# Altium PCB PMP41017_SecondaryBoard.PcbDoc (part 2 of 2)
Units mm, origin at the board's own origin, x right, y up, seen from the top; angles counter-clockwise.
Board outline 59.94 x 50.1 mm, 4 copper layers (Top Layer, Layer 1, Layer 2, Bottom Layer), stack 1.926 mm thick; 120 components, 60 nets, 831 pads, 509 vias.
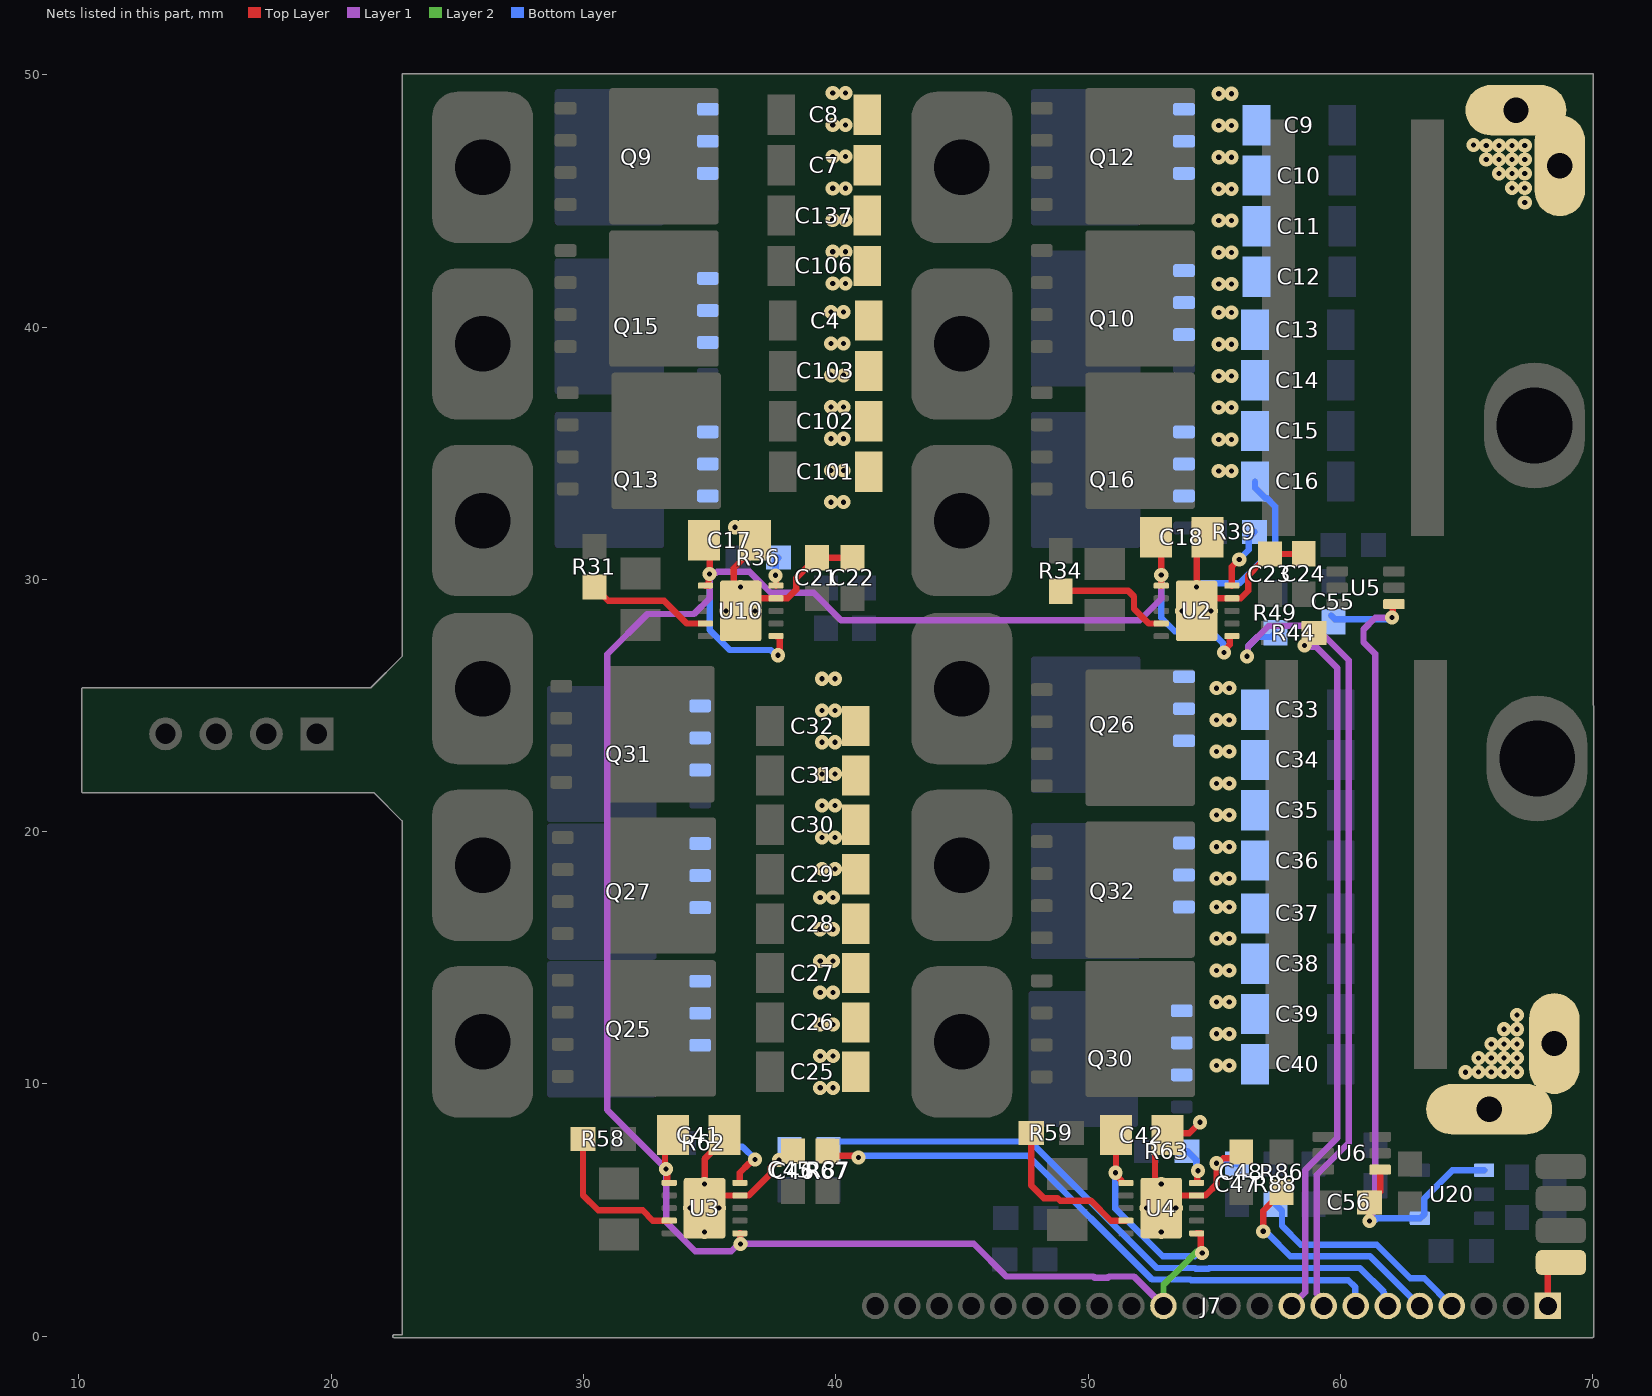
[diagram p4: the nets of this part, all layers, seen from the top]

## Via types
v1: diameter 0.559, hole 0.203, Top Layer to Bottom Layer, tented both sides, 490 vias
v2: diameter 0.559, hole 0.203, Top Layer to Bottom Layer, 14 vias
v3: diameter 0.7, hole 0.35, Top Layer to Bottom Layer, 4 vias
v4: diameter 0.762, hole 0.356, Top Layer to Bottom Layer, tented both sides, 1 vias

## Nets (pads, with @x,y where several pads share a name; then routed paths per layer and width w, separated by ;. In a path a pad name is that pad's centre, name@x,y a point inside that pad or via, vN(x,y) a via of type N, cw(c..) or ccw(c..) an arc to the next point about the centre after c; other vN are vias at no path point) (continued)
SR1_BH: J7.9 R44.1 | length 28.4
  Top Layer w0.254: v1(58.585,27.38) 58.585,27.531 58.933,27.879 R44.1@58.958,27.879
  Layer 1 w0.254: J7.9@58.07,1.2 58.611,1.74 58.611,6.59 59.878,7.858 59.878,26.489 59.036,27.331 58.634,27.331 v1(58.585,27.38)
SR1_BL: J7.8 R49.1 | length 33.2
  Layer 1 w0.254: v1(56.3,26.952) 56.34,26.992 56.34,27.338 57.163,28.161 58.965,28.161 60.332,26.793 60.332,7.67 59.065,6.402 59.065,1.691 59.34,1.415 J7.8@59.34,1.2
  Bottom Layer w0.254: v1(56.3,26.952) 56.34,26.992 56.34,27.338 56.719,27.717 57.261,27.717 R49.1@57.427,27.883
SR2_AH: J7.7 R67.1 | length 24
  Top Layer w0.254: R67.1@39.663,7.343 39.856,7.15 40.746,7.15 40.812,7.085 v1(40.894,7.085)
  Bottom Layer w0.254: v1(40.894,7.085) 40.941,7.132 41.115,7.132 41.133,7.15 47.633,7.15 52.533,2.251 54.055,2.251 54.085,2.221 60.317,2.221 60.587,1.95 60.587,1.223 J7.7@60.61,1.2
SR2_AL: J7.6 R87.1 | length 25.3
  Bottom Layer w0.254: R87.1@39.716,7.404 40.032,7.72 47.706,7.72 52.721,2.705 54.243,2.705 54.273,2.675 54.775,2.675 54.805,2.705 60.774,2.705 61.728,1.75 61.728,1.352 J7.6@61.88,1.2
SR2_BH: J7.5 R86.1 | length 9.3
  Top Layer w0.254: v1(56.946,4.159) 56.946,4.976 57.302,5.332 57.327,5.332 57.675,5.68 R86.1@57.675,5.705
  Bottom Layer w0.254: v1(56.946,4.159) 57.015,4.159 57.142,4.032 57.16,4.032 58.018,3.175 61.175,3.175 J7.5@63.15,1.2
SR2_BL: J7.4 R88.1 | length 9
  Bottom Layer w0.254: R88.1@57.427,5.23 57.689,4.968 57.689,4.374 58.434,3.629 61.439,3.629 62.776,2.293 63.328,2.293 J7.4@64.42,1.2
V0-out: C4.2 C7.2 C8.2 C9.2 C10.2 C11.2 C12.2 C13.2 C14.2 C15.2 C16.2 C17.2 C18.2 C21.1 C22.1 C23.1 C24.1 C25.2 C26.2 C27.2 C28.2 C29.2 C30.2 C31.2 C32.2 C33.2 C34.2 C35.2 C36.2 C37.2 C38.2 C39.2 C40.2 C41.2 C42.2 C45.1 C46.1 C47.1 C48.1 C101.2 C102.2 C103.2 C106.2 C137.2 J7.1 pad.4@65.9,9 pad.4@66.963,48.6 pad.4@68.7,46.4 pad.4@68.481,11.6 pad.9 Q9.1 Q9.2 Q9.3 Q10.1 Q10.2 Q10.3 Q12.1 Q12.2 Q12.3 Q13.1 Q13.2 Q13.3 Q15.1 Q15.2 Q15.3 Q16.1 Q16.2 Q16.3 Q25.1 Q25.2 Q25.3 Q26.1 Q26.2 Q26.3 Q27.1 Q27.2 Q27.3 Q30.1 Q30.2 Q30.3 Q31.1 Q31.2 Q31.3 Q32.1 Q32.2 Q32.3 U2.9 U2.11 U3.9 U3.11 U4.9 U4.11 U10.9 U10.11 | length 42.6
  Top Layer w0.254: U3.11@34.798,5.08 35.298,5.58 U3.9@36.198,5.58 36.551,5.58 37.4,6.429 37.4,6.683 37.701,6.984 37.962,6.984 38.032,7.055 C46.1@38.032,7.305 ; v2(34.798,6.03) 34.798,7.026 35.582,7.81 C41.2@35.582,7.975 ; C17.2@36.805,31.56 36.297,31.052 36.297,30.774 35.961,30.438 35.961,29.022 U10.11@36.23,28.753 36.73,29.253 38.089,29.253 38.426,29.589 38.426,30.049 38.862,30.485 38.898,30.485 39.246,30.833 C21.1@39.246,30.858 C22.1@40.666,30.858 ; U2.11@54.302,28.753 54.802,29.253 U2.9@55.702,29.253 56.055,29.253 56.351,29.549 56.351,30.154 56.832,30.635 56.857,30.635 57.205,30.983 C23.1@57.205,31.008 58.542,31.008 C24.1@58.55,31.016 ; v2(54.302,29.703) 54.302,31.141 C18.2@54.721,31.56 ; v1(54.443,8.481) 54.01,8.049 53.217,8.049 C42.2@53.143,7.975 52.652,7.484 52.652,5.33 U4.11@52.902,5.08 53.402,5.58 U4.9@54.302,5.58 54.641,5.58 54.694,5.633 54.708,5.633 55.091,6.016 55.091,6.857 55.157,6.858 55.355,7.056 55.824,7.056 C48.1@56.073,7.305 ; J7.1@68.23,1.2 68.23,2.537 68.594,2.901 pad.9@68.746,2.901
  Bottom Layer w0.254: v1(37.753,6.984) C45.1@38.173,7.404 ; v2(54.302,29.703) 54.384,29.703 54.534,29.852 56.005,29.852 57.427,31.274 57.427,32.883 57.1,33.21 57.041,33.21 56.618,33.633 C16.2@56.618,33.883 ; v1(55.09,6.858) 55.867,6.858 C47.1@55.895,6.83
  other v1: 39.382,9.847 39.89,9.847 64.969,10.464 65.477,10.475 65.985,10.475 66.493,10.475 67.001,10.475 55.09,10.731 55.598,10.731 65.477,11.032 65.985,11.033 66.493,11.033 67.001,11.033 39.382,11.105 39.89,11.105 65.985,11.581 66.493,11.581 67.001,11.581 55.09,11.988 55.598,11.988 66.493,12.167 67.001,12.167 39.382,12.362 39.89,12.362 67.001,12.73 55.09,13.246 55.598,13.246 39.382,13.62 39.89,13.62 55.09,14.503 55.598,14.503 39.382,14.877 39.89,14.877 55.09,15.76 55.598,15.76 39.382,16.135 39.89,16.135 55.09,17.018 55.598,17.018 39.382,17.392 39.89,17.392 55.09,18.143 55.598,18.143 39.457,18.518 39.965,18.518 55.09,19.401 55.598,19.401 39.457,19.775 39.965,19.775 55.09,20.658 55.598,20.658 39.457,21.032 39.965,21.032 55.09,21.916 55.598,21.916 39.457,22.29 39.965,22.29 55.09,23.173 55.598,23.173 39.457,23.547 39.965,23.547 55.09,24.431 55.598,24.431 39.457,24.805 39.965,24.805 55.09,25.688 55.598,25.688 39.457,26.062 39.965,26.062 36.006,32.067 39.803,33.061 40.311,33.061 55.181,34.294 55.689,34.294 39.803,34.319 40.311,34.319 55.181,35.551 55.689,35.551 39.803,35.576 40.311,35.576 55.181,36.808 55.689,36.808 39.803,36.834 40.311,36.834 55.181,38.066 55.689,38.066 39.803,38.091 40.311,38.091 55.181,39.323 55.689,39.323 39.803,39.348 40.311,39.348 55.181,40.581 55.689,40.581 39.803,40.606 40.311,40.606 55.181,41.706 55.689,41.706 39.878,41.732 40.386,41.732 55.181,42.964 55.689,42.964 39.878,42.989 40.386,42.989 55.181,44.221 55.689,44.221 39.878,44.246 40.386,44.246 67.31,44.948 55.181,45.479 55.689,45.479 39.878,45.504 40.386,45.504 66.802,45.511 67.31,45.511 66.294,46.097 66.802,46.097 67.31,46.097 65.786,46.646 66.294,46.645 66.802,46.645 67.31,46.645 55.181,46.736 55.689,46.736 39.878,46.761 40.386,46.761 65.278,47.214 65.786,47.203 66.294,47.203 66.802,47.203 67.31,47.203 55.181,47.993 55.689,47.993 39.878,48.019 40.386,48.019 55.181,49.251 55.689,49.251 39.878,49.276 40.386,49.276
  other v2: 34.798,4.13 52.902,4.13 34.223,5.08 35.373,5.08 52.327,5.08 53.477,5.08 52.902,6.03 35.655,28.753 36.805,28.753 53.727,28.753 54.877,28.753 36.23,29.703
VDD: C17.1 C18.1 C41.1 C42.1 J7.13 U2.1 U2.6 U3.1 U3.6 U4.1 U4.6 U10.1 U10.6 | length 101.2
  Top Layer w0.25: U3.1@33.398,6.08 33.393,6.085 33.323,6.085 33.323,6.582 v1(33.274,6.631) 33.234,6.672 33.234,7.658 C41.1@33.55,7.975 ; C42.1@51.111,7.975 51.111,6.507 v1(51.086,6.482) 51.086,6.412 51.327,6.171 U4.1@51.327,6.085
  Top Layer w0.254: C17.1@34.76,31.661 34.83,31.591 C17.1@34.83,31.503 ; C17.1@34.773,31.56 C17.1@34.83,31.503 ; U10.1@34.83,29.753 34.946,29.753 34.953,29.76 34.953,30.163 v1(35,30.21) 35,31.333 C17.1@34.83,31.503 ; U3.6@36.198,4.08 36.207,4.08 36.214,4.073 36.214,3.677 v1(36.23,3.661) ; U10.6@37.63,27.753 37.768,27.753 37.775,27.746 37.775,27.142 37.711,27.077 v1(37.711,26.995) ; C18.1@52.689,31.56 52.902,31.347 v1(52.902,30.178) U2.1@52.902,29.753 ; U4.6@54.302,4.08 54.468,4.08 54.475,4.073 54.475,3.346 v1(54.524,3.297) ; v1(55.395,27.108) 55.395,27.189 55.615,27.409 55.615,27.746 55.622,27.753 U2.6@55.702,27.753
  Layer 1 w0.254: v1(52.902,30.178) 52.902,29.238 52.051,28.387 40.207,28.387 39.126,29.468 37.424,29.468 36.583,30.309 35.301,30.309 35.26,30.268 35.058,30.268 v1(35,30.21) 35,29.248 34.381,28.63 32.534,28.63 30.935,27.031 30.935,8.97 v1(33.274,6.631) 33.274,4.527 34.43,3.371 35.857,3.371 36.147,3.661 v1(36.23,3.661) 45.463,3.661 46.756,2.368 50.215,2.368 50.272,2.311 50.774,2.311 50.832,2.368 51.822,2.368 J7.13@52.99,1.2
  Layer 2 w0.254: J7.13@52.99,1.2 52.99,2.038 53.633,2.681 54.295,3.342 54.297,3.339 54.482,3.339 v1(54.524,3.297)
  Bottom Layer w0.254: v1(35,30.21) 35,27.995 35.792,27.204 37.422,27.204 37.631,26.995 v1(37.711,26.995) ; v1(51.086,6.482) 51.086,5.049 52.959,3.175 54.223,3.175 54.287,3.239 54.466,3.239 v1(54.524,3.297) ; v1(52.902,30.178) 52.902,28.485 53.441,27.945 54.877,27.945 55.363,27.46 55.363,27.14 v1(55.395,27.108)
VG_SR1_AH: R31.1 U10.4 | length 5
  Top Layer w0.254: R31.1@30.43,29.703 30.43,29.678 30.778,29.33 30.803,29.33 30.977,29.156 33.194,29.156 34.097,28.253 U10.4@34.83,28.253
VG_SR1_AL: R36.1 U10.10 | length 1.2
  Top Layer w0.254: U10.10@37.63,29.753 37.63,30.17 v1@37.63,30.178
  Bottom Layer w0.254: v1(37.615,30.163) 37.615,30.753 R36.1@37.726,30.864
VG_SR1_BH: R34.1 U2.4 | length 4.8
  Top Layer w0.254: R34.1@48.917,29.534 48.926,29.543 51.601,29.543 51.821,29.323 51.821,28.839 52.407,28.253 U2.4@52.902,28.253
VG_SR1_BL: R39.1 U2.10 | length 2.6
  Top Layer w0.254: U2.10@55.702,29.753 55.702,30.503 v1(55.995,30.796) v1@55.93,30.796
  Bottom Layer w0.254: v1(55.995,30.796) 56.376,31.177 56.376,31.661 R39.1@56.6,31.884
VG_SR2_AH: R58.1 U3.4 | length 6.1
  Top Layer w0.254: R58.1@29.978,7.823 29.978,5.589 30.579,4.989 32.342,4.989 32.751,4.58 U3.4@33.398,4.58
VG_SR2_AL: R62.1 U3.10 | length 2.7
  Top Layer w0.254: U3.10@36.198,6.08 36.198,6.483 36.561,6.846 36.568,6.846 36.721,6.999 v1(36.803,6.999)
  Bottom Layer w0.254: R62.1@35.566,7.662 35.712,7.516 36.299,7.516 36.803,7.011 v1(36.803,6.999)
VG_SR2_BH: R59.1 U4.4 | length 6.4
  Top Layer w0.254: R59.1@47.747,8.059 47.747,5.975 48.245,5.477 48.785,5.477 48.893,5.369 50.116,5.369 50.905,4.58 U4.4@51.502,4.58
VG_SR2_BL: R63.1 U4.10 | length 1.5
  Top Layer w0.254: U4.10@54.302,6.08 54.324,6.08 54.331,6.087 54.331,6.531 v1(54.359,6.56)
  Bottom Layer w0.254: R63.1@53.917,7.332 53.942,7.332 54.29,6.984 54.29,6.695 54.359,6.626 v1(54.359,6.56)
Vref: C55.2 C56.2 U5.1 U6.1 U20.1 U20.4 | length 36.2
  Top Layer w0.254: v1(61.154,4.562) 61.154,5.063 61.278,5.186 C56.2@61.156,5.307 61.181,5.307 61.529,5.655 61.529,5.68 61.576,5.727 U6.1@61.576,6.605 ; v1(62.042,28.486) 62.084,28.527 62.084,28.947 62.157,29.02 U5.1@62.169,29.02
  Layer 1 w0.254: v1(61.154,4.562) 61.213,4.62 61.213,4.798 61.384,4.969 61.384,27.046 60.917,27.512 60.917,28.017 61.386,28.486 v1(62.042,28.486)
  Bottom Layer w0.254: C55.2@59.64,28.57 59.781,28.429 61.985,28.429 v1(62.042,28.486) ; v1(61.154,4.562) 61.213,4.62 61.393,4.62 61.452,4.679 U20.4@63.15,4.679 63.173,4.679 63.321,4.827 63.321,5.457 64.443,6.579 U20.1@65.7,6.579
pads on no net: Q1.9@31.279,44.4 Q1.9@31.279,49.145 Q1.9@31.574,45.442 Q1.9@31.574,46.772 Q1.9@31.574,48.102 Q1.9@32.724,45.442 Q1.9@32.724,46.772 Q1.9@32.724,48.102 Q1.9@32.859,46.772 Q1.9@33.874,45.442 Q1.9@33.874,46.772 Q1.9@33.874,48.102 Q2.9@50.153,38.76 Q2.9@50.153,43.505 Q2.9@50.448,39.803 Q2.9@50.448,41.133 Q2.9@50.448,42.463 Q2.9@51.598,39.803 Q2.9@51.598,41.133 Q2.9@51.598,42.463 Q2.9@51.733,41.133 Q2.9@52.748,39.803 Q2.9@52.748,41.133 Q2.9@52.748,42.463 Q4.9@50.153,44.4 Q4.9@50.153,49.145 Q4.9@50.448,45.442 Q4.9@50.448,46.772 Q4.9@50.448,48.102 Q4.9@51.598,45.442 Q4.9@51.598,46.772 Q4.9@51.598,48.102 Q4.9@51.733,46.772 Q4.9@52.748,45.442 Q4.9@52.748,46.772 Q4.9@52.748,48.102 Q5.9@31.366,33.121 Q5.9@31.366,37.866 Q5.9@31.661,34.163 Q5.9@31.661,35.493 Q5.9@31.661,36.823 Q5.9@32.811,34.163 Q5.9@32.811,35.493 Q5.9@32.811,36.823 Q5.9@32.946,35.493 Q5.9@33.961,34.163 Q5.9@33.961,35.493 Q5.9@33.961,36.823 Q7.9@31.279,38.76 Q7.9@31.279,43.505 Q7.9@31.574,39.803 Q7.9@31.574,41.133 Q7.9@31.574,42.463 Q7.9@32.724,39.803 Q7.9@32.724,41.133 Q7.9@32.724,42.463 Q7.9@32.859,41.133 Q7.9@33.874,39.803 Q7.9@33.874,41.133 Q7.9@33.874,42.463 Q8.9@50.153,33.121 Q8.9@50.153,37.866 Q8.9@50.448,34.163 Q8.9@50.448,35.493 Q8.9@50.448,36.823 Q8.9@51.598,34.163 Q8.9@51.598,35.493 Q8.9@51.598,36.823 Q8.9@51.733,35.493 Q8.9@52.748,34.163 Q8.9@52.748,35.493 Q8.9@52.748,36.823 Q9.9@30.344,45.402 Q9.9@30.344,46.732 Q9.9@30.344,48.062 Q9.9@31.359,46.732 Q9.9@31.494,45.402 Q9.9@31.494,46.732 Q9.9@31.494,48.062 Q9.9@32.644,45.402 Q9.9@32.644,46.732 Q9.9@32.644,48.062 Q9.9@32.939,44.36 Q9.9@32.939,49.105 Q10.9@49.218,39.007 Q10.9@49.218,40.337 Q10.9@49.218,41.667 Q10.9@50.233,40.337 Q10.9@50.368,39.007 Q10.9@50.368,40.337 Q10.9@50.368,41.667 Q10.9@51.518,39.007 Q10.9@51.518,40.337 Q10.9@51.518,41.667 Q10.9@51.813,37.965 Q10.9@51.813,42.71 Q12.9@49.218,45.402 Q12.9@49.218,46.732 Q12.9@49.218,48.062 Q12.9@50.233,46.732 Q12.9@50.368,45.402 Q12.9@50.368,46.732 Q12.9@50.368,48.062 Q12.9@51.518,45.402 Q12.9@51.518,46.732 Q12.9@51.518,48.062 Q12.9@51.813,44.36 Q12.9@51.813,49.105 Q13.9@30.344,32.613 Q13.9@30.344,33.943 Q13.9@30.344,35.273 Q13.9@31.359,33.943 Q13.9@31.494,32.613 Q13.9@31.494,33.943 Q13.9@31.494,35.273 Q13.9@32.644,32.613 Q13.9@32.644,33.943 Q13.9@32.644,35.273 Q13.9@32.939,31.57 Q13.9@32.939,36.315 Q15.9@30.344,38.698 Q15.9@30.344,40.028 Q15.9@30.344,41.358 Q15.9@31.359,40.028 Q15.9@31.494,38.698 Q15.9@31.494,40.028 Q15.9@31.494,41.358 Q15.9@32.644,38.698 Q15.9@32.644,40.028 Q15.9@32.644,41.358 Q15.9@32.939,37.656 Q15.9@32.939,42.401 Q16.9@49.218,32.613 Q16.9@49.218,33.943 Q16.9@49.218,35.273 Q16.9@50.233,33.943 Q16.9@50.368,32.613 Q16.9@50.368,33.943 Q16.9@50.368,35.273 Q16.9@51.518,32.613 Q16.9@51.518,33.943 Q16.9@51.518,35.273 Q16.9@51.813,31.57 Q16.9@51.813,36.315 Q17.9@31.112,21.488 Q17.9@31.112,26.233 Q17.9@31.407,22.531 Q17.9@31.407,23.861 Q17.9@31.407,25.191 Q17.9@32.557,22.531 Q17.9@32.557,23.861 Q17.9@32.557,25.191 Q17.9@32.692,23.861 Q17.9@33.707,22.531 Q17.9@33.707,23.861 Q17.9@33.707,25.191 Q18.9@50.156,21.352 Q18.9@50.156,26.097 Q18.9@50.451,22.394 Q18.9@50.451,23.724 Q18.9@50.451,25.054 Q18.9@51.601,22.394 Q18.9@51.601,23.724 Q18.9@51.601,25.054 Q18.9@51.736,23.724 Q18.9@52.751,22.394 Q18.9@52.751,23.724 Q18.9@52.751,25.054 Q21.9@31.166,9.834 Q21.9@31.166,14.579 Q21.9@31.461,10.876 Q21.9@31.461,12.206 Q21.9@31.461,13.536 Q21.9@32.611,10.876 Q21.9@32.611,12.206 Q21.9@32.611,13.536 Q21.9@32.746,12.206 Q21.9@33.761,10.876 Q21.9@33.761,12.206 Q21.9@33.761,13.536 Q22.9@50.153,9.81 Q22.9@50.153,14.555 Q22.9@50.448,10.852 Q22.9@50.448,12.182 Q22.9@50.448,13.512 Q22.9@51.598,10.852 Q22.9@51.598,12.182 Q22.9@51.598,13.512 Q22.9@51.733,12.182 Q22.9@52.748,10.852 Q22.9@52.748,12.182 Q22.9@52.748,13.512 Q23.9@31.166,15.492 Q23.9@31.166,20.237 Q23.9@31.461,16.534 Q23.9@31.461,17.864 Q23.9@31.461,19.194 Q23.9@32.611,16.534 Q23.9@32.611,17.864 Q23.9@32.611,19.194 Q23.9@32.746,17.864 Q23.9@33.761,16.534 Q23.9@33.761,17.864 Q23.9@33.761,19.194 Q24.9@50.153,15.33 Q24.9@50.153,20.075 Q24.9@50.448,16.372 Q24.9@50.448,17.702 Q24.9@50.448,19.032 Q24.9@51.598,16.372 Q24.9@51.598,17.702 Q24.9@51.598,19.032 Q24.9@51.733,17.702 Q24.9@52.748,16.372 Q24.9@52.748,17.702 Q24.9@52.748,19.032 Q25.9@30.037,10.838 Q25.9@30.037,12.168 Q25.9@30.037,13.498 Q25.9@31.052,12.168 Q25.9@31.187,10.838 Q25.9@31.187,12.168 Q25.9@31.187,13.498 Q25.9@32.337,10.838 Q25.9@32.337,12.168 Q25.9@32.337,13.498 Q25.9@32.632,9.795 Q25.9@32.632,14.54 Q26.9@49.218,22.908 Q26.9@49.218,24.238 Q26.9@49.218,25.568 Q26.9@50.233,24.238 Q26.9@50.368,22.908 Q26.9@50.368,24.238 Q26.9@50.368,25.568 Q26.9@51.518,22.908 Q26.9@51.518,24.238 Q26.9@51.518,25.568 Q26.9@51.813,21.866 Q26.9@51.813,26.611 Q27.9@30.037,16.293 Q27.9@30.037,17.623 Q27.9@30.037,18.953 Q27.9@31.052,17.623 Q27.9@31.187,16.293 Q27.9@31.187,17.623 Q27.9@31.187,18.953 Q27.9@32.337,16.293 Q27.9@32.337,17.623 Q27.9@32.337,18.953 Q27.9@32.632,15.251 Q27.9@32.632,19.996 Q30.9@49.125,9.665 Q30.9@49.125,10.995 Q30.9@49.125,12.325 Q30.9@50.14,10.995 Q30.9@50.275,9.665 Q30.9@50.275,10.995 Q30.9@50.275,12.325 Q30.9@51.72,8.622 Q30.9@51.72,13.367 Q30.9@51.425,9.665 Q30.9@51.425,10.995 Q30.9@51.425,12.325 Q31.9@30.037,21.749 Q31.9@30.037,23.079 Q31.9@30.037,24.409 Q31.9@31.052,23.079 Q31.9@31.187,21.749 Q31.9@31.187,23.079 Q31.9@31.187,24.409 Q31.9@32.337,21.749 Q31.9@32.337,23.079 Q31.9@32.337,24.409 Q31.9@32.632,20.707 Q31.9@32.632,25.452 Q32.9@49.218,16.318 Q32.9@49.218,17.648 Q32.9@49.218,18.978 Q32.9@50.233,17.648 Q32.9@50.368,16.318 Q32.9@50.368,17.648 Q32.9@50.368,18.978 Q32.9@51.518,16.318 Q32.9@51.518,17.648 Q32.9@51.518,18.978 Q32.9@51.813,15.275 Q32.9@51.813,20.02 U2.2 U3.2 U4.2 U10.2

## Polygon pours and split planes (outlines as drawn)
12Vout on Top Layer "TOP_LAYER_12VOUT_P055" (solid, remove dead copper, pour order 55): 60.873,10.479 64.206,10.479 67.814,14.087 69.74,14.087 69.74,16.013 69.74,43.568 67.814,43.568 64.32,47.062 64.32,49.756 60.873,49.756
V0-out on Top Layer "TOP_LAYER_V0-OUT_P070" (solid, remove dead copper, pour order 70): 62.758,7.786 62.758,9.955 66.655,13.851 69.74,13.851 69.74,8.78 68.746,7.786
12Vo_B on Top Layer "TOP_LAYER_12VO_B_P065" (solid, remove dead copper, pour order 65): 58.908,27.38 49.53,27.38 49.53,8.895 59.553,8.895 59.586,8.928 59.586,26.702
LV_SW2B on Top Layer "TOP_LAYER_LV_SW2B_P064" (solid, remove dead copper, pour order 64): 42.418,28.668 48.024,28.668 49.18,27.512 49.18,10.261 47.587,8.668 43.148,8.668 42.418,9.398
V0-out on Top Layer "TOP_LAYER_V0-OUT_P063" (solid, remove dead copper, pour order 63): 38.862,26.633 41.489,26.633 41.843,26.278 41.843,8.78 38.862,8.78
V0-out on Top Layer "TOP_LAYER_V0-OUT_P052" (solid, remove dead copper, pour order 52): 64.539,49.846 64.539,47.171 67.927,43.782 69.85,43.782 69.85,49.338 69.342,49.846
12Vo_B on Top Layer "TOP_LAYER_12VO_B_P060" (solid, remove dead copper, pour order 60): 30.789,26.633 37.239,26.633 38.02,25.852 38.02,9.074 31.113,9.074 30.789,9.398
LV_SW2A on Top Layer "TOP_LAYER_LV_SW2A_P058" (solid, remove dead copper, pour order 58): 22.999,28.668 28.144,28.668 30.109,26.704 30.109,9.398 28.769,8.059 22.999,8.059
12Vo_A on Top Layer "TOP_LAYER_12VO_A_P051" (solid, remove dead copper, pour order 51): 49.96,49.846 59.459,49.846 59.459,31.976 59.057,31.574 49.98,31.574 49.378,32.177 49.378,49.265
LV_SW1B on Top Layer "TOP_LAYER_LV_SW1B_P050" (solid, remove dead copper, pour order 50): 42.418,29.267 42.418,49.36 43.058,50 48.864,50 49.108,49.755 49.108,30.254 48.121,29.267
V0-out on Top Layer "TOP_LAYER_V0-OUT_P048" (solid, remove dead copper, pour order 48): 39.283,49.846 41.91,49.846 42.265,49.492 42.265,31.994 39.283,31.994
12Vo_A on Top Layer "TOP_LAYER_12VO_A_P047" (solid, remove dead copper, pour order 47): 38.704,49.846 38.704,41.633 38.704,31.085 31.269,31.085 30.309,32.045 30.309,49.156 31,49.846
LV_SW1A on Top Layer "TOP_LAYER_LV_SW1A_P044" (solid, remove dead copper, pour order 44): 22.86,50 30.309,50 30.309,31.56 28.083,29.333 24.272,29.333 22.999,30.607
V0-out on Bottom Layer "BOTTOM_LAYER_V0-OUT_P069" (solid, remove dead copper, pour order 69): 63.796,7.124 69.74,7.124 69.74,14.246 62.954,14.246 62.719,14.011 62.719,8.2
12Vout on Bottom Layer "BOTTOM_LAYER_12VOUT_P057" (solid, remove dead copper, pour order 57): 62.436,40.671 69.394,40.671 69.74,40.324 69.74,15.278 62.436,15.278
12Vo_B on Bottom Layer "BOTTOM_LAYER_12VO_B_P068" (solid, remove dead copper, pour order 68): 60.434,8.07 61.275,8.911 61.275,26.742 57.897,26.742 57.897,8.07
V0-out on Bottom Layer "BOTTOM_LAYER_V0-OUT_P067" (solid, remove dead copper, pour order 67): 53.708,27.46 56.196,27.46 57.427,26.229 57.427,8.07 52.99,8.07 52.99,26.742
LV_SW2B on Bottom Layer "BOTTOM_LAYER_LV_SW2B_P066" (solid, remove dead copper, pour order 66): 42.714,8.116 52.1,8.116 52.555,8.571 52.555,27.766 51.361,28.96 43.822,28.96 41.843,26.981 41.843,8.988
V0-out on Bottom Layer "BOTTOM_LAYER_V0-OUT_P062" (solid, remove dead copper, pour order 62): 34.007,10.056 35.075,8.988 41.519,8.988 41.519,26.458 41.481,26.495 34.273,26.495 34.007,26.229
LV_SW2A on Bottom Layer "BOTTOM_LAYER_LV_SW2A_P061" (solid, remove dead copper, pour order 61): 23.014,28.668 32.674,28.668 33.451,27.891 33.451,8.891 32.631,8.071 24.002,8.071 22.999,9.074
V0-out on Bottom Layer "BOTTOM_LAYER_V0-OUT_P054" (solid, remove dead copper, pour order 54): 69.342,40.965 62.436,40.965 62.436,49.846 69.342,49.846 69.85,49.338 69.85,41.473
V0-out on Bottom Layer "BOTTOM_LAYER_V0-OUT_P046" (solid, remove dead copper, pour order 46): 33.8,31.722 42.265,31.722 42.265,49.492 41.91,49.846 34.498,49.846 33.8,49.148
12Vo_A on Bottom Layer "BOTTOM_LAYER_12VO_A_P056" (solid, remove dead copper, pour order 56): 60.764,32.256 61.275,32.768 61.275,49.846 57.897,49.846 57.897,32.256
V0-out on Bottom Layer "BOTTOM_LAYER_V0-OUT_P053" (solid, remove dead copper, pour order 53): 53.086,49.846 57.205,49.846 57.205,40.128 57.205,33.324 56.6,32.718 53.467,32.718 53.277,32.909
LV_SW1B on Bottom Layer "BOTTOM_LAYER_LV_SW1B_P049" (solid, remove dead copper, pour order 49): 42.926,48.768 44.004,49.846 52.223,49.846 52.578,49.492 52.578,30.758 52.324,30.504 51.021,29.201 43.058,29.201 42.926,29.333
LV_SW1A on Bottom Layer "BOTTOM_LAYER_LV_SW1A_P045" (solid, remove dead copper, pour order 45): 22.999,49.846 33.101,49.846 33.8,49.148 33.8,30.325 32.655,29.181 24.425,29.181 23.014,30.592
LV_SW2A on Layer 1 "LAYER_1_LV_SW2A_P078" (solid, remove dead copper, pour order 78): 28.916,8.05 28.916,29.122 28.703,29.334 23.585,29.334 22.952,28.7 22.952,8.755 23.642,8.065
LV_SW1A on Layer 1 "LAYER_1_LV_SW1A_P077" (solid, remove dead copper, pour order 77): 28.914,29.046 28.914,49.788 28.702,50 23.584,50 22.95,49.366 22.95,29.421 23.309,29.062
V0-out on Layer 1 "LAYER_1_V0-OUT_P076" (solid, remove dead copper, pour order 76): 63.669,4.868 69.74,4.868 69.74,14.246 62.954,14.246 62.719,14.011 62.719,5.817
12Vout on Layer 1 "LAYER_1_12VOUT_P075" (solid, remove dead copper, pour order 75): 60.972,40.671 69.394,40.671 69.74,40.324 69.74,15.278 60.972,15.278
V0-out on Layer 1 "LAYER_1_V0-OUT_P074" (solid, remove dead copper, pour order 74): 69.342,40.965 60.972,40.965 60.972,49.846 69.342,49.846 69.85,49.338 69.85,41.473
12Vo_B on Layer 1 "LAYER_1_12VO_B_P071" (solid, remove dead copper, pour order 71): 30.681,6.482 58.596,6.482 60.566,8.452 60.566,28.194 30.756,28.194
12Vo_A on Layer 1 "LAYER_1_12VO_A_P059" (solid, remove dead copper, pour order 59): 28.914,28.956 58.991,28.956 60.565,30.53 60.565,49.938 60.503,50 28.987,50
V0-out on Layer 2 "Layer 2-V0-out" (solid, remove dead copper, pour order 72): 28.956,0.476 69.981,0.476 69.981,16.98 64.269,16.98 62.423,18.826 62.422,39.662 63.781,41.022 69.98,41.022 69.98,50 28.956,50
LV_SW2A on Layer 2 "LAYER_2_LV_SW2A_P080" (solid, remove dead copper, pour order 80): 28.916,7.998 28.916,29.122 28.703,29.334 23.585,29.334 22.952,28.7 22.952,8.755 23.694,8.013
LV_SW1A on Layer 2 "LAYER_2_LV_SW1A_P079" (solid, remove dead copper, pour order 79): 28.914,29.046 28.914,49.788 28.702,50 23.584,50 22.95,49.366 22.95,29.421 23.309,29.062
12Vout on Layer 2 "LAYER_2_12VOUT_P073" (solid, remove dead copper, pour order 73): 69.996,17.267 64.401,17.267 62.738,18.93 62.738,39.624 63.885,40.771 69.791,40.771 69.981,40.581

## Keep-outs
Keep-Out Layer:
  text ".Layer_Name" at -20.343,-59.464 h1.52

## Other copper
Top Layer:
  text ".Layer_Name" at -20.343,-59.464 h1.52
Bottom Layer:
  text ".Layer_Name" at -20.343,-59.464 h1.52

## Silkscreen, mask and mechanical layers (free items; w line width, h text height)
Top Overlay:
  text "'.PRJ_Number'.PCB_Rev" at 24.384,0.762 h2.75
  text ".Layer_Name" at -20.343,-59.464 h1.52
Bottom Overlay:
  text ".Layer_Name" at -20.343,-59.464 h1.52
Top Paste:
  text ".Layer_Name" at -20.343,-59.464 h1.52
Bottom Paste:
  text ".Layer_Name" at -20.343,-59.464 h1.52
Top Solder:
  text ".Layer_Name" at -20.343,-59.464 h1.52
  text ".Layer_Name" at -20.343,-59.464 h1.52
Bottom Solder:
  text ".Layer_Name" at -20.343,-59.464 h1.52
Drill Guide:
  text ".Layer_Name" at -20.343,-59.464 h1.52
M1 Board Outline:
  lines w0.1: 22.479,0 70,0 69.98,50 22.86,50 22.86,26.924 21.59,25.654 10.16,25.654 10.16,21.59 21.336,21.59 21.717,21.59 22.86,20.447 22.86,0 ; 69.98,0 69.98,0
  text ".Layer_Name" at -20.343,-59.464 h1.52
M2 Board Dimensions:
  rectangle: -34.999,-44.643 -31.824,-41.468
  rectangle: -31.824,-47.818 -22.299,-44.643
  lines w0.178: -34.999,-44.643 -9.599,-44.643 ; -31.824,-47.818 -31.824,-41.468 ; -28.649,-47.818 -28.649,-41.468 ; -22.299,-47.818 -22.299,-41.468 ; -15.949,-47.818 -15.949,-41.468 ; -34.999,-47.818 -9.599,-47.818 -9.599,-41.468 -34.999,-41.468 -34.999,-47.818
  text ".Layer_Name" at -20.343,-59.464 h1.52
M3 3D STEP Top:
  text ".Layer_Name" at -20.343,-59.464 h1.52
M4 3D STEP Bottom:
  text ".Layer_Name" at -20.343,-59.464 h1.52
M5 Assembly Top:
  lines w0.254: -42.416,-61.285 125.224,-61.285 ; -42.416,-56.12 125.275,-56.12 ; -42.416,-50.955 -42.416,-66.449 59.311,-66.449 125.275,-66.449 125.275,-50.955 -42.403,-50.955 -42.403,-66.449 -2.386,-66.449 ; 20.195,-66.449 20.195,-50.955 ; 52.377,-56.12 52.377,-50.955 ; 73.713,-56.12 73.713,-50.955 ; 89.512,-66.614 89.512,-61.463
  text "COMPONENTS MARKED 'DNP' SHOULD NOT BE POPULATED." at -5.7,-45.748 h1.52
  text "ASSEMBLY VARIANT:" at -5.713,-48.682 h1.52
  text ".VariantName" at 20.601,-48.682 h1.52
  text "PCB VIEWED FROM TOP SIDE" at -40.803,-54.312 h1.52
  text "BOARD #:" at 22.1,-54.312 h1.52
  text ".PRJ_Number" at 35.956,-54.312 h1.52
  text "REV:" at 57.406,-54.312 h1.52
  text ".PCB_Rev" at 64.81,-54.312 h1.52
  text "SVN REV:" at 78.691,-54.312 h1.52
  text ".VersionControl_RevNumber" at 91.544,-54.312 h1.52
  text "TID #:" at 22.1,-59.477 h1.52
  text ".TID" at 35.956,-59.477 h1.52
  text "PLOT NAME =" at -40.803,-64.693 h1.52
  text ".plot_File_Name" at -20.343,-64.693 h1.52
  text "GENERATED    :" at 22.151,-64.693 h1.52
  text ".Print_Date" at 44.236,-64.693 h1.52
  text ".Print_Time" at 62.753,-64.693 h1.52
  text "TEXAS INSTRUMENTS" at 94.871,-64.693 h1.52
M6 Assembly Bottom:
  lines w0.254: -42.429,-56.133 125.262,-56.133 ; -42.378,-61.297 125.262,-61.297 ; -6.665,-66.627 -6.665,-61.475 ; 9.133,-56.133 9.133,-50.968 ; 30.469,-56.133 30.469,-50.968 ; 62.651,-66.462 62.651,-50.968 ; 85.232,-66.462 125.249,-66.462 125.249,-50.968 -42.429,-50.968 -42.429,-66.462 23.535,-66.462 125.262,-66.462 125.262,-50.968
  text "COMPONENTS MARKED 'DNP' SHOULD NOT BE POPULATED." at 119.992,-45.736 h1.52
  text ".VariantName" at 93.474,-48.682 h1.52
  text "ASSEMBLY VARIANT:" at 119.865,-48.682 h1.52
  text ".VersionControl_RevNumber" at -8.697,-54.325 h1.52
  text "SVN REV:" at 4.155,-54.325 h1.52
  text ".PCB_Rev" at 18.036,-54.325 h1.52
  text "REV:" at 25.44,-54.325 h1.52
  text ".PRJ_Number" at 46.89,-54.325 h1.52
  text "BOARD #:" at 60.746,-54.325 h1.52
  text "PCB VIEWED FROM BOTTOM SIDE" at 123.649,-54.325 h1.52
  text ".TID" at 46.89,-59.49 h1.52
  text "TID #:" at 60.746,-59.49 h1.52
  text "TEXAS INSTRUMENTS" at -12.025,-64.705 h1.52
  text ".Print_Time" at 20.093,-64.705 h1.52
  text ".Print_Date" at 38.61,-64.705 h1.52
  text "GENERATED    :" at 60.695,-64.705 h1.52
  text ".plot_File_Name" at 103.19,-64.705 h1.52
  text "PLOT NAME =" at 123.649,-64.705 h1.52
M9 Title Sheet:
  drawing of 57 lines, arcs and shapes, not listed
  text "1" at -16.207,166.469 h1.78
  text "2" at 47.183,166.469 h1.78
  text "3" at 110.412,166.469 h1.78
  text "4" at 174.081,166.469 h1.78
  text "5" at 237.556,166.469 h1.78
  text "6" at 301.183,166.469 h1.78
  text "A" at -45.578,137.436 h1.78
  text "A" at 330.342,137.436 h1.78
  text "B" at -45.578,76.984 h1.78
  text "B" at 330.342,76.984 h1.78
  text "C" at -45.578,16.659 h1.78
  text "C" at 330.342,16.659 h1.78
  text "PROJECT TITLE:" at 253.126,-30.61 h1.14
  text ".PRJ_Title" at 254.396,-33.996 h1.78
  text "DESIGNED FOR:" at 253.126,-38.255 h1.14
  text ".PRJ_Customer" at 254.396,-41.811 h1.78
  text "D" at -45.578,-43.539 h1.78
  text "D" at 330.342,-43.539 h1.78
  text "FILE NAME:" at 253.126,-45.875 h1.14
  text ".PCB_File_Name_No_Path" at 254.396,-48.923 h1.78
  text "Texas Instruments (TI) and/or its licensors do not warrant the accuracy or completeness of this specification" at 126.9,-53.034 h1.14
  text "ENGINEER:" at 253.126,-53.241 h1.14
  text "LAYOUT BY:" at 291.353,-53.241 h1.14
  text "or any information contained therein. TI and/or its licensors do not warrant that this design will meet" at 125.758,-55.896 h1.14
  text ".PRJ_Engineer" at 254.396,-57.178 h1.78
  text ".PCB_Layout" at 292.635,-57.178 h1.78
  text "the specifications, will be suitable for your application or fit for any particular purpose, or will operate in" at 125.758,-58.757 h1.14
  text ".Layer_Name" at -20.343,-59.464 h1.52
  text "ALTIUM DESIGNER VERSION:" at 291.353,-61.115 h1.14
  text "an implementation. TI and/or its licensors do not warrant that the design is production worthy. You should" at 125.758,-61.619 h1.14
  text "completely validate and test your design implementation to confirm the system functionality for your application." at 126.9,-64.481 h1.14
  text ".print_Scale" at 254.396,-64.502 h1.78
  text ".Application_BuildNumber" at 292.635,-64.502 h1.78
  text "1" at -16.207,-69.751 h1.78
  text "2" at 47.183,-69.751 h1.78
  text "3" at 110.412,-69.751 h1.78
  text "4" at 174.081,-69.751 h1.78
  text "5" at 237.556,-69.751 h1.78
  text "6" at 301.183,-69.751 h1.78
M10 Fab Notes:
  drawing of 189 lines, arcs and shapes, not listed
  text "DESIGN INFORMATION" at 279.504,123.788 h1.52
  text "MIN. TRACK WIDTH:" at 263.132,120.432 h1.52
  text "8" at 290.977,120.432 h1.52
  text "MIL" at 294.908,120.432 h1.52
  text "7.874" at 286.751,117.342 h1.52
  text "MIN. CLEARANCE:" at 263.132,117.28 h1.52
  text "MIL" at 294.908,117.28 h1.52
  text "MIN. VIA PAD SIZE:" at 263.132,114.127 h1.52
  text "24" at 290.215,114.127 h1.52
  text "MIL" at 294.908,114.127 h1.52
  text "0.05mm (2MIL)" at 280.785,110.827 h1.52
  text "MINIMUM ANNULAR RING" at 254.77,110.618 h1.52
  text "EXTERNAL" at 298.769,110.618 h1.52
  text "PER" at 259.85,107.821 h1.52
  text "IPC-D-275 CLASS 2 LEVEL C" at 265.438,107.821 h1.52
  text "MIL, HOLES" at 303.239,105.269 h1.52
  text "+/-" at 293.27,105.051 h1.52
  text "+/-" at 314.962,105.051 h1.52
  text "REGISTRATION TOLERANCES:" at 254.77,105.024 h1.52
  text "METAL" at 285.244,105.024 h1.52
  text "5" at 299.88,105.024 h1.52
  text "3" at 321.038,105.024 h1.52
  text "MIL" at 323.991,105.024 h1.52
  text "HOLE SIZE TOLERANCE (UNLESS OTHERWISE SPECIFIED):" at 254.77,102.527 h1.52
  text "+/-" at 314.962,102.454 h1.52
  text "3" at 321.038,102.427 h1.52
  text "MIL" at 323.991,102.427 h1.52
  text "MATERIAL:" at 252.871,98.931 h1.52
  text "FR-4 High Tg" at 277.926,95.666 h1.52
  text "X" at 274.258,95.463 h1.52
  text "FR-408" at 263.564,95.348 h1.52
  text "OTHER" at 301.359,95.348 h1.52
  text "62 MIL (1.6mm) +/-10%" at 271.695,91.715 h1.52
  text "X" at 268.644,91.653 h1.52
  text "THICKNESS:" at 254.77,91.507 h1.52
  text "OTHER" at 304.331,91.507 h1.52
  text "TOLERANCE:" at 254.77,87.993 h1.52
  text "X" at 276.315,87.993 h1.52
  text "ANSI IPC-6012 TYPE 3 CLASS 2" at 280.837,87.993 h1.52
  text "OTHER +/-" at 280.836,84.331 h1.52
  text "BOW & TWIST:" at 254.77,80.643 h1.52
  text "X" at 276.315,80.643 h1.52
  text "ANSI IPC-6012 TYPE 3 CLASS 2" at 280.837,80.643 h1.52
  text "OTHER +/-" at 280.836,76.917 h1.52
  text "DRILLING:" at 252.871,73.599 h1.52
  text "NC_DRILL FILES" at 297.6,70.928 h1.52
  text "REFERENCE:" at 254.77,70.828 h1.52
  text "X" at 271.464,70.825 h1.52
  text "AS SHOWN" at 275.985,70.828 h1.52
  text "X" at 294.349,70.828 h1.52
  text "OTHER" at 305.169,67.214 h1.52
  text "PTH COPPER THICKNESS:" at 254.762,67.125 h1.52
  text "X" at 283.698,67.125 h1.52
  text "20-30 um" at 286.949,67.125 h1.52
  text "BOARD FINISH:" at 252.871,63.376 h1.52
  text "SILKSCREEN:" at 256.813,60.579 h1.52
  text "X" at 281.141,60.579 h1.52
  text "TOP" at 284.113,60.579 h1.52
  text "X" at 294.095,60.579 h1.52
  text "BOTTOM" at 297.092,60.579 h1.52
  text "SILKSCREEN COLOR:" at 256.813,56.637 h1.52
  text "X" at 281.116,56.637 h1.52
  text "WHITE" at 284.113,56.637 h1.52
  text "OTHER" at 297.092,56.637 h1.52
  text "X" at 284.443,52.993 h1.52
  text "GREEN" at 287.44,52.993 h1.52
  text "OTHER" at 303.137,52.993 h1.52
  text "SOLDER RESIST COLOR:" at 256.813,52.819 h1.52
  text "X" at 284.443,49.075 h1.52
  text "MATTE" at 287.44,49.075 h1.52
  text "SEMI-GLOSS" at 303.126,49.059 h1.52
  text "IMMERSION GOLD (ENIG)" at 279.82,44.687 h1.52
  text "ENEPIG" at 313.794,44.503 h1.52
  text "SURFACE FINISH:" at 252.871,44.478 h1.52
  text "X" at 275.299,44.478 h1.52
  text "IMM. TIN/SILVER OR EQUIV" at 261.241,40.99 h1.52
  text "OTHER" at 297.6,40.89 h1.52
  text "ARRAY/PANEL:" at 252.871,36.944 h1.52
  text "CUT AND TRIM PER M1 BOARD OUTLINE" at 279.82,36.735 h1.52
  text "N.C. ROUTE" at 279.82,33.281 h1.52
  text "X" at 297.295,33.281 h1.52
  text "V. SCORE" at 301.817,33.281 h1.52
  text "CERTIFICATION:" at 252.871,30.001 h1.52
  text "MATERIALS AND WORKMANSHIP FOR ALL PCBS" at 271.286,30.001 h1.52
  text "TO MEET OR EXCEED THE REQUIREMENTS OF:" at 271.286,27.612 h1.52
  text "X" at 262.078,24.345 h1.52
  text "ANSI IPC-A-600F CLASS ->" at 265.33,24.345 h1.52
  text "X" at 307.189,24.345 h1.52
  text "2" at 309.983,24.345 h1.52
  text "1" at 301.982,24.307 h1.52
  text "3" at 318.974,24.307 h1.52
  text "X" at 282.703,20.594 h1.52
  text "RoHS" at 285.954,20.594 h1.52
  text "OTHER" at 302.322,20.594 h1.52
  text "PER ORDER" at 312.407,20.594 h1.52
  text "ALL BOARDS MUST MEET OR EXCEED UL94-V0 REQUIREMENTS." at 253.57,16.687 h1.52
  text "PCB MUST BEAR THE UL94V-0 UL REGISTERED MATERIAL ID NUMBER" at 253.57,13.739 h1.52
  text "ADDITIONAL REQUIREMENTS:" at 252.871,9.435 h1.52
  text "MICROSECTION:" at 254.77,6.714 h1.52
  text "YES" at 277.776,6.714 h1.52
  text "REQUIRED" at 299.658,3.048 h1.52
  text "BARE BOARD ELEC. TEST:" at 254.77,2.976 h1.52
  text "NONE" at 287.936,2.976 h1.52
  text "X" at 296.66,2.976 h1.52
  text "PER ORDER" at 314.694,2.976 h1.52
  text "XX MIL VIAS REQUIRE NON-CONDUCTIVE FILL AND PLANARIZE" at 259.041,-2.23 h1.5
  text "XX MIL VIAS REQUIRE CONDUCTIVE FILL AND PLANARIZE" at 259.244,-4.871 h1.52
  text "OUTER XX MIL TRACES REQUIRE 50 OHM SINGLE-ENDED IMPEDANCE" at 259.219,-9.021 h1.47
  text "LAYER 2 & 3 (INNER LAYERS) XX MIL WIDE, XX MIL SPACE / TRACES REQUIRE 100 OHM DIFFERENTIAL IMPEDANCE" at 259.016,-15.008 h1.52
  text ".Layer_Name" at -20.343,-59.464 h1.52
M11 Gerber Information:
  lines w0.254: -42.416,-61.285 125.224,-61.285 ; -42.416,-56.12 125.275,-56.12 ; -42.416,-50.955 -42.416,-66.449 59.311,-66.449 125.275,-66.449 125.275,-50.955 -42.403,-50.955 -42.403,-66.449 -2.386,-66.449 ; 20.195,-66.449 20.195,-50.955 ; 52.377,-56.12 52.377,-50.955 ; 73.713,-56.12 73.713,-50.955 ; 89.512,-66.614 89.512,-61.463
  text "ALL ARTWORK VIEWED FROM TOP SIDE" at -40.803,-54.312 h1.52
  text "BOARD #:" at 22.1,-54.312 h1.52
  text ".PRJ_Number" at 35.956,-54.312 h1.52
  text "REV:" at 57.406,-54.312 h1.52
  text ".PCB_Rev" at 64.81,-54.312 h1.52
  text "SVN REV:" at 78.691,-54.312 h1.52
  text ".VersionControl_RevNumber" at 91.544,-54.312 h1.52
  text "LAYER NAME =" at -40.803,-59.464 h1.52
  text "TID #:" at 22.1,-59.477 h1.52
  text ".TID" at 35.956,-59.477 h1.52
  text "PLOT NAME =" at -40.803,-64.693 h1.52
  text ".plot_File_Name" at -20.343,-64.693 h1.52
  text "GENERATED    :" at 22.151,-64.693 h1.52
  text ".Print_Date" at 44.236,-64.693 h1.52
  text ".Print_Time" at 62.753,-64.693 h1.52
  text "TEXAS INSTRUMENTS" at 94.871,-64.693 h1.52
M12 Stackup:
  drawing of 337 lines, arcs and shapes, not listed
  text "Layer" at 214.469,162.365 h1.52
  text "Name" at 224.881,162.365 h1.52
  text "Material" at 248.497,162.365 h1.52
  text "Thickness" at 270.335,162.365 h1.52
  text "Constant" at 286.841,162.365 h1.52
  text "Board Layer Stack" at 301.315,162.365 h1.52
  text "Top Overlay" at 224.881,159.317 h1.52
  text "Top Solder" at 224.881,156.269 h1.52
  text "Solder Resist" at 248.497,156.269 h1.52
  text "0.40mil" at 270.335,156.269 h1.52
  text "3.5" at 286.841,156.269 h1.52
  text "1" at 214.469,153.221 h1.52
  text "Top Layer" at 224.881,153.221 h1.52
  text "CF-005" at 248.497,153.221 h1.52
  text "2.76mil" at 270.335,153.221 h1.52
  text "Dielectric 1" at 224.881,150.173 h1.52
  text "PP-006" at 248.497,150.173 h1.52
  text "2.80mil" at 270.335,150.173 h1.52
  text "4.1" at 286.841,150.173 h1.52
  text "2" at 214.469,147.125 h1.52
  text "Layer 1" at 224.881,147.125 h1.52
  text "CF-005" at 248.497,147.125 h1.52
  text "2.76mil" at 270.335,147.125 h1.52
  text "Dielectric1" at 224.881,144.077 h1.52
  text "FR-4 High Tg" at 248.497,144.077 h1.52
  text "59.20mil" at 270.335,144.077 h1.52
  text "4.8" at 286.841,144.077 h1.52
  text "3" at 214.469,141.029 h1.52
  text "Layer 2" at 224.881,141.029 h1.52
  text "CF-005" at 248.497,141.029 h1.52
  text "2.76mil" at 270.335,141.029 h1.52
  text "Dielectric 2" at 224.881,137.981 h1.52
  text "PP-006" at 248.497,137.981 h1.52
  text "2.80mil" at 270.335,137.981 h1.52
  text "4.1" at 286.841,137.981 h1.52
  text "4" at 214.469,134.933 h1.52
  text "Bottom Layer" at 224.881,134.933 h1.52
  text "CF-005" at 248.497,134.933 h1.52
  text "2.76mil" at 270.335,134.933 h1.52
  text "Bottom Solder" at 224.881,131.885 h1.52
  text "Solder Resist" at 248.497,131.885 h1.52
  text "0.40mil" at 270.335,131.885 h1.52
  text "3.5" at 286.841,131.885 h1.52
  text "Bottom Overlay" at 224.881,128.837 h1.52
  text "GaN Board2" at 7.848,45.352 h0.89
  text "Transformer1" at 32.648,38.752 h0.89
  text "Resonant Choke 1&2" at 3.648,33.652 h0.89
  text "Board_CST" at 7.178,20.129 h0.89
  text "Transformer2" at 33.848,18.252 h0.89
  text "GaN Board1" at 6.448,12.152 h0.89
  text "Flyback" at 12.657,4.449 h0.89
  text "McU Board" at 49.457,2.352 h0.89
  text ".Layer_Name" at -20.343,-59.464 h1.52
M13 Component Bodies Top:
  text ".Layer_Name" at -20.343,-59.464 h1.52
M14 Component Bodies Bottom:
  text ".Layer_Name" at -20.343,-59.464 h1.52
M15 Courtyards Top:
  text ".Layer_Name" at -20.343,-59.464 h1.52
M16 Courtyards Bottom:
  text ".Layer_Name" at -20.343,-59.464 h1.52
Drill Drawing:
  lines w0.254: 91.775,24.712 92.125,24.712 92.125,24.362 92.827,24.362 92.827,24.712 93.178,24.712 93.178,25.414 92.827,25.414 92.827,25.765 92.125,25.765 92.125,25.414 91.775,25.414 91.775,24.712 ; 91.775,27.87 92.125,27.87 92.125,27.519 92.827,27.519 92.827,27.87 93.178,27.87 93.178,28.572 92.827,28.572 92.827,28.923 92.125,28.923 92.125,28.572 91.775,28.572 91.775,27.87 ; 91.775,33.835 91.775,34.186 92.125,34.537 91.775,34.887 91.775,35.238 92.125,35.238 92.476,34.887 92.827,35.238 93.178,35.238 93.178,34.887 92.827,34.537 93.178,34.186 93.178,33.835 92.827,33.835 92.476,34.186 92.125,33.835 91.775,33.835 ; 91.775,38.396 93.178,38.396 92.476,36.993 91.775,38.396 ; 91.775,40.501 92.125,40.501 92.476,40.15 92.827,40.501 93.178,40.501 92.827,40.852 93.178,41.203 92.827,41.203 92.476,41.554 92.125,41.203 91.775,41.203 92.125,40.852 91.775,40.501 ; 91.775,43.308 93.178,43.308 93.178,44.711 91.775,44.711 91.775,43.308 ; 92.055,28.011 92.266,28.011 92.266,27.8 92.687,27.8 92.687,28.011 92.897,28.011 92.897,28.432 92.687,28.432 92.687,28.642 92.266,28.642 92.266,28.432 92.055,28.432 92.055,28.011 ; 92.055,34.115 92.055,34.326 92.266,34.537 92.055,34.747 92.055,34.958 92.266,34.958 92.476,34.747 92.687,34.958 92.897,34.958 92.897,34.747 92.687,34.537 92.897,34.326 92.897,34.115 92.687,34.115 92.476,34.326 92.266,34.115 92.055,34.115
  lines w0.305: 90.502,17.099 172.582,17.099 ; 90.502,45.518 172.582,45.518 ; 99.084,13.941 99.084,48.676 ; 107.517,13.941 107.517,48.676 ; 123.685,13.941 123.685,48.676 ; 130.268,13.941 130.268,48.676 ; 139.797,13.941 139.797,48.676 ; 158.195,13.941 158.195,48.676 ; 90.502,13.941 172.582,13.941 172.582,48.676 90.502,48.676 90.502,13.941
  text "Symbol" at 92.397,46.466 h1.83
  text "Quantity" at 100.031,46.466 h1.83
  text "Finished Hole Size" at 108.464,46.466 h1.83
  text "Plated" at 124.633,46.466 h1.83
  text "Hole Type" at 131.215,46.466 h1.83
  text "Drill Layer Pair" at 140.744,46.466 h1.83
  text "Hole Tolerance" at 159.142,46.466 h1.83
  text "504" at 100.031,43.308 h1.52
  text "8.00mil (0.203mm)" at 108.464,43.308 h1.52
  text "PTH" at 124.633,43.308 h1.52
  text "Round" at 131.215,43.308 h1.52
  text "Top Layer - Bottom Layer" at 140.744,43.308 h1.52
  text "4" at 100.031,40.15 h1.52
  text "13.78mil (0.350mm)" at 108.464,40.15 h1.52
  text "PTH" at 124.633,40.15 h1.52
  text "Round" at 131.215,40.15 h1.52
  text "Top Layer - Bottom Layer" at 140.744,40.15 h1.52
  text "1" at 100.031,36.993 h1.52
  text "14.00mil (0.356mm)" at 108.464,36.993 h1.52
  text "PTH" at 124.633,36.993 h1.52
  text "Round" at 131.215,36.993 h1.52
  text "Top Layer - Bottom Layer" at 140.744,36.993 h1.52
  text "22" at 100.031,33.835 h1.52
  text "27.56mil (0.700mm)" at 108.464,33.835 h1.52
  text "PTH" at 124.633,33.835 h1.52
  text "Round" at 131.215,33.835 h1.52
  text "Top Layer - Bottom Layer" at 140.744,33.835 h1.52
  text "4" at 100.031,30.677 h1.52
  text "31.89mil (0.810mm)" at 108.464,30.677 h1.52
  text "PTH" at 124.633,30.677 h1.52
  text "Round" at 131.215,30.677 h1.52
  text "Top Layer - Bottom Layer" at 140.744,30.677 h1.52
  text "+/-1.97mil" at 159.142,30.677 h1.52
  text "I" at 91.988,30.423 h1.4
  text "2" at 100.031,27.519 h1.52
  text "118.11mil (3.000mm)" at 108.464,27.519 h1.52
  text "PTH" at 124.633,27.519 h1.52
  text "Round" at 131.215,27.519 h1.52
  text "Top Layer - Bottom Layer" at 140.744,27.519 h1.52
  text "12" at 100.031,24.362 h1.52
  text "86.61mil (2.200mm)" at 108.464,24.362 h1.52
  text "PTH" at 124.633,24.362 h1.52
  text "Rectangle" at 131.215,24.362 h1.52
  text "Top Layer - Bottom Layer" at 140.744,24.362 h1.52
  text "3" at 100.031,21.204 h1.52
  text "39.37mil (1.000mm)" at 108.464,21.204 h1.52
  text "PTH" at 124.633,21.204 h1.52
  text "Slot" at 131.215,21.204 h1.52
  text "Top Layer - Bottom Layer" at 140.744,21.204 h1.52
  text "A" at 91.755,20.95 h1.4
  text "1" at 100.031,18.046 h1.52
  text "39.37mil (1.000mm)" at 108.464,18.046 h1.52
  text "PTH" at 124.633,18.046 h1.52
  text "Slot" at 131.215,18.046 h1.52
  text "Top Layer - Bottom Layer" at 140.744,18.046 h1.52
  text "G" at 91.755,17.792 h1.4
  text "553 Total" at 100.031,14.888 h1.52
  text "Slot definitions :" at 92.397,12.678 h1.52
  text "Routed Path Length" at 103.845,12.678 h1.52
  text "= Calculated from tool start centre position to tool end centre position." at 117.554,12.678 h1.52
  text "Hole Length" at 103.845,11.415 h1.52
  text "= Routed Path Length + Tool Size = Slot length as defined in the PCB layout" at 112.48,11.415 h1.52
  text ".Layer_Name" at -20.343,-59.464 h1.52
M17 Embedded Cavity:
  text ".Layer_Name" at -20.343,-59.464 h1.52
M18 Embedded Assembly:
  text ".Layer_Name" at -20.343,-59.464 h1.52
M19 Embedded Keepout:
  text ".Layer_Name" at -20.343,-59.464 h1.52

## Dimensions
0,0 to 22.86,50 on M2 Board Dimensions
-0.005,-0.017 to 70.005,0 on M2 Board Dimensions
-34.999,-47.818 to -9.599,-47.818 on M2 Board Dimensions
